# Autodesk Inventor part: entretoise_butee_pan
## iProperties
Created: 2011-01
Part Number: entretoise_butee_pan
Document SubType Name: Modeling
Designer: eric
Density: 1 g/cm^3
Mass: 0.0348717 g
Surface Area: 1.51111 cm^2
Volume: 0.0348717 cm^3
Author: eric
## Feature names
1. Base1
